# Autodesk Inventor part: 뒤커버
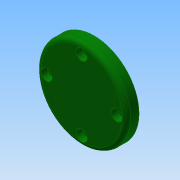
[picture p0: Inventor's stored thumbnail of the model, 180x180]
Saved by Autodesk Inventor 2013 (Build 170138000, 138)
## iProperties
Created: 2019-01
Part Number: 뒤커버
Material: 알루미늄 6061
Document SubType Name: Modeling
Designer: mduedu
Density: 2.71 g/cm^3
Mass: 73.1938 g
Surface Area: 93.0687 cm^2
Volume: 27.0088 cm^3
Author: mduedu
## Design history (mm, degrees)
sketch "스케치1"
  geometry: L1 (0, 0)-(9, 0); L2 (9, 0)-(9, 32); L3 (9, 32)-(0, 32); L4 (0, 32)-(0, 0); L5 (9, 0)-(12, 0); L6 (12, 0)-(12, 20); L7 (12, 20)-(9, 20); L8 (9, 20)-(9, 0)
  constraints: 16 end point, 4 parallel, 2 horizontal, 2 perpendicular
  dimensions: "d0" = 12 distance between parallel lines of L6 L4; "d2" = 64 diameter of L3 L1; "d3" = 40 diameter of L7 L5; "d4" = 3 distance between parallel lines of L6 L2
revolve "회전1" sketch "스케치1" stored, may be unused: angle "d5" = 90 deg
sketch "스케치4"
  geometry: C1 r 15 at (0, 0); 1 further point
  constraints: 1 centre point, 1 coincident
  dimensions: "d24" = 30 diameter of C1
extrude "돌출1" cut sketch "스케치4" distance "d25" = 6; taper "d26" = 0 deg
fillet "모깎기4" dims "d27" = 3
fillet "모깎기3" dims "d18" = 3
chamfer "모따기2" distance "d28" = 1; stored, may be unused: second distance "d29" = 2, angle "d30" = 45 deg
sketch "스케치3" dims "d19" = 50
  geometry: 6 further points
  constraints: 2 vertical alignment, 1 coincident, 7 other
  dimensions: "d22" = 360 deg dimension on point (0, 0) point (0, 25) (derived)
sketch "스케치5"
  geometry: 4 further points
  constraints: 4 other
hole "구멍1" sketch "스케치5" at (-25, 0), (0, -25), (25, 0), (0, 25) diameter "d31" = 4.5; stored, may be unused: countersink angle "d35" = 90 deg, drill point angle "d37" = 0 deg; dims "d32" = 6, "d33" = 8, "d34" = 4.6, "d36" = 8
node "솔리드1"
